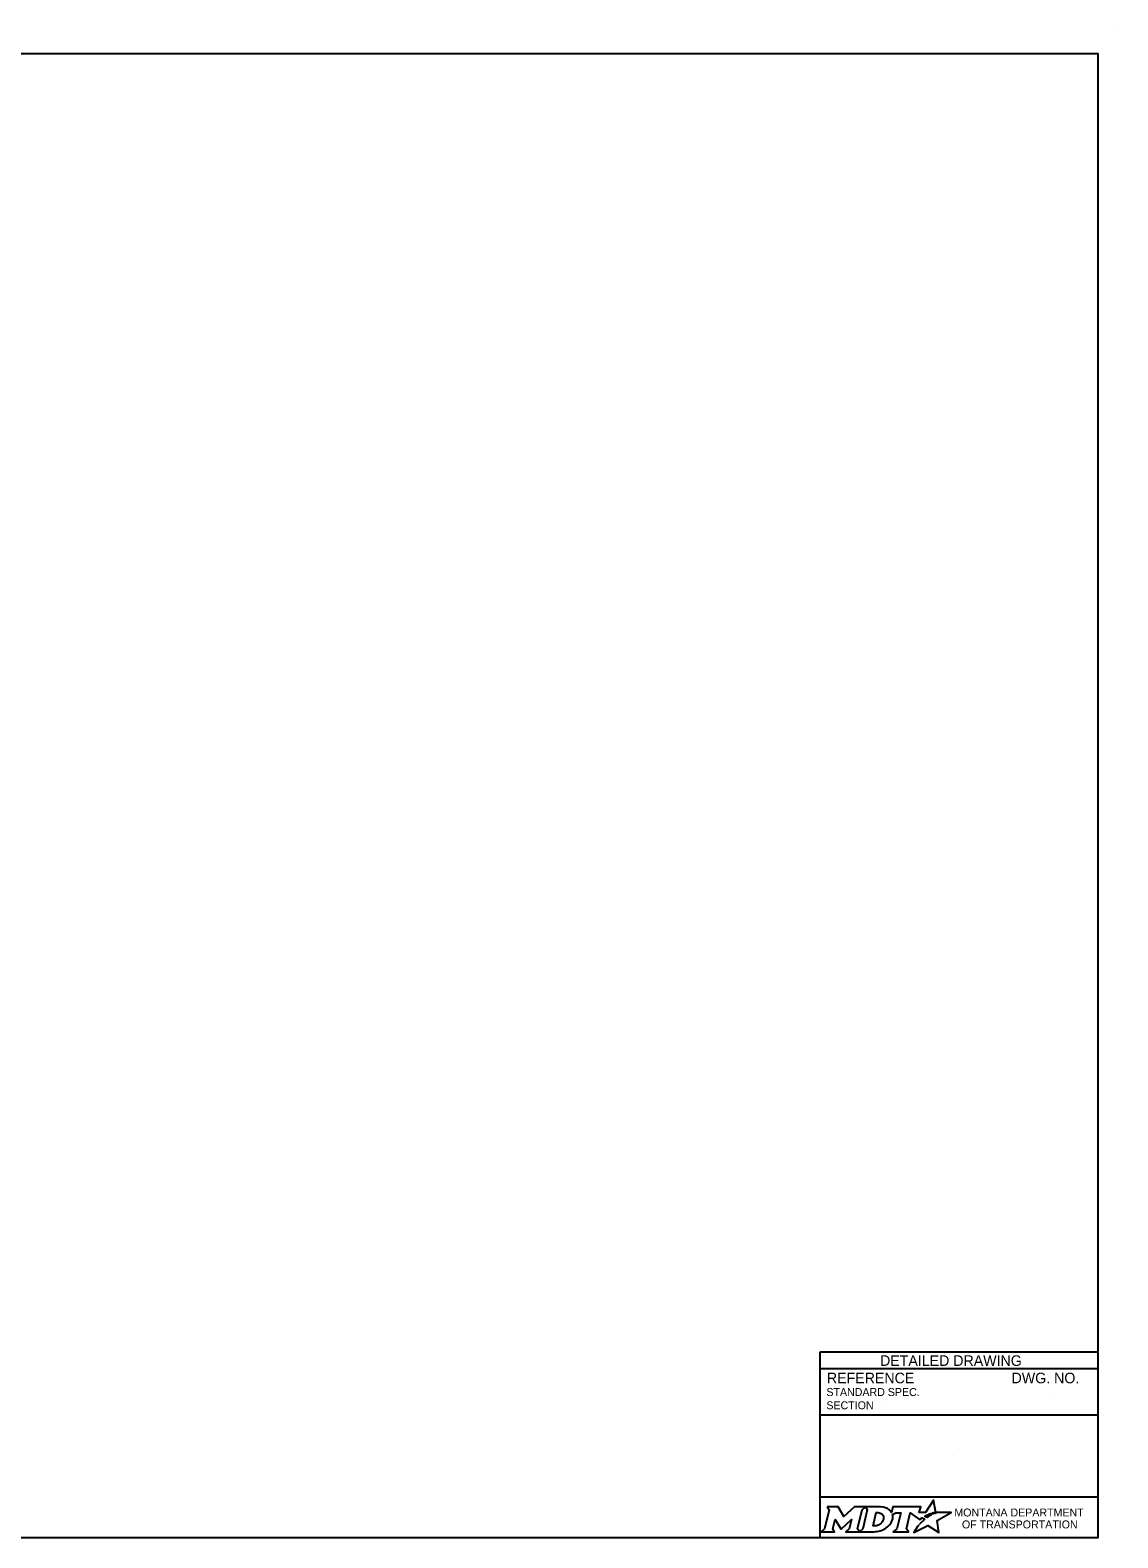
# Model space of a CAD drawing. Extents: x 49990.8 to 50021, y 49987.6 to 50011.4.
# Drawn here: x 50008.69 to 50016.9, y 49987.8 to 49999.18 of the extents above; entities that cross this region are included whole.
import ezdxf

# ---------------------------------------------------------------- set-up
doc = ezdxf.new("R2010")
doc.units = 0
for name, color, linetype in [('Default', 7, 'Continuous'), ('Level 1', 7, 'Continuous'), ('Level 5', 7, 'Continuous')]:
    doc.layers.add(name, color=color, linetype=linetype)

msp = doc.modelspace()

# ---------------------------------------------------------------- linework, layer by layer
at = {"layer": 'Default'}
for points in [[(50015.513, 49987.981), (50015.502, 49987.987), (50015.514, 49987.99), (50015.526, 49987.991), (50015.508, 49988.082), (50015.449, 49987.99), (50015.401, 49987.99), (50015.412, 49988.034), (50015.202, 49988.034), (50015.192, 49987.991), (50015.186, 49988)], [(50014.706, 49988.034), (50014.72, 49988.01), (50014.686, 49987.867), (50014.66, 49987.845), (50014.762, 49987.845), (50014.749, 49987.867), (50014.765, 49987.937), (50014.809, 49987.868), (50014.814, 49987.868), (50014.889, 49987.938), (50014.872, 49987.867), (50014.848, 49987.845), (50014.949, 49987.845), (50014.936, 49987.868), (50014.969, 49988.011)], [(50014.969, 49988.011), (50014.994, 49988.034), (50014.912, 49988.034), (50014.832, 49987.961), (50014.788, 49988.034), (50014.706, 49988.034)], [(50015.108, 49988.034), (50014.994, 49988.034), (50015.009, 49988.011), (50014.975, 49987.867), (50014.949, 49987.845), (50015.06, 49987.845)], [(50015.132, 49987.947), (50015.13, 49987.939), (50015.127, 49987.93), (50015.123, 49987.922), (50015.118, 49987.914), (50015.111, 49987.907), (50015.103, 49987.901), (50015.095, 49987.896), (50015.086, 49987.892), (50015.077, 49987.89), (50015.067, 49987.889), (50015.052, 49987.889), (50015.075, 49987.989), (50015.091, 49987.989), (50015.099, 49987.988), (50015.106, 49987.986), (50015.113, 49987.983), (50015.119, 49987.979), (50015.124, 49987.974), (50015.128, 49987.968), (50015.13, 49987.962), (50015.132, 49987.955), (50015.132, 49987.952), (50015.132, 49987.947)], [(50015.199, 49987.975), (50015.224, 49987.988), (50015.261, 49987.988), (50015.232, 49987.867), (50015.205, 49987.845), (50015.321, 49987.845), (50015.304, 49987.867), (50015.332, 49987.988), (50015.403, 49987.936), (50015.424, 49987.951), (50015.444, 49987.94)], [(50015.388, 49987.884), (50015.373, 49987.86), (50015.368, 49987.852), (50015.362, 49987.844), (50015.36, 49987.839), (50015.465, 49987.893), (50015.549, 49987.838), (50015.536, 49987.93), (50015.643, 49987.989), (50015.594, 49987.989), (50015.564, 49987.99), (50015.543, 49987.99), (50015.536, 49987.989), (50015.531, 49987.987), (50015.523, 49987.985), (50015.513, 49987.981)], [(50015.462, 49987.954), (50015.46, 49987.952), (50015.442, 49987.961), (50015.452, 49987.967), (50015.456, 49987.969), (50015.465, 49987.973), (50015.47, 49987.976), (50015.478, 49987.979), (50015.485, 49987.982), (50015.497, 49987.974), (50015.493, 49987.972), (50015.489, 49987.97), (50015.484, 49987.967), (50015.479, 49987.965), (50015.478, 49987.963), (50015.475, 49987.962), (50015.472, 49987.96), (50015.47, 49987.959), (50015.467, 49987.957), (50015.465, 49987.955), (50015.462, 49987.954)], [(50015.106, 49987.852), (50015.114, 49987.855), (50015.127, 49987.86), (50015.148, 49987.871)], [(50015.402, 49987.9), (50015.402, 49987.9)]]:
    msp.add_lwpolyline(points, dxfattribs=at)
for centre, radius, start, end in [((50015.087, 49987.973), 0.118, 300.9103, 339.1383), ((50015.131, 49987.955), 0.0709, 339.5329, 15.8582)]:
    msp.add_arc(centre, radius, start, end, dxfattribs=at)
for centre, major_axis, ratio, start_param, end_param in [((50015.106, 49987.986), (0.0834, -0.0037), 0.568097, 0.61298, 1.570796), ((50015.161, 49987.994), (0.0361, -0.0295), 0.469099, 1.225588, 1.570796), ((50015.433, 49987.93), (-0.0112, -0.0097), 0.021651, 3.157348, 6.283185), ((50015.06, 49987.993), (0, 0.148), 0.987302, 3.139398, 3.456847), ((50015.395, 49987.892), (-0.00694, -0.00806), 0.008222, 0, 3.137361), ((50015.412, 49987.911), (-0.0098, -0.0102), 0.016458, 3.141593, 6.279097)]:
    msp.add_ellipse(centre, major_axis=major_axis, ratio=ratio, start_param=start_param, end_param=end_param, dxfattribs=at)
at = {"layer": 'Level 1'}
msp.add_line((50016.9, 49999.176), (50016.9, 49999.176), dxfattribs=at)
msp.add_lwpolyline([(49999.384, 49998.999), (50016.75, 49998.999), (50016.75, 49987.799), (49999.384, 49987.799)], close=True, dxfattribs=at)
at = {"layer": 'Level 5'}
for p, q in [((50016.75, 49989.199), (50014.65, 49989.199)), ((50014.65, 49989.199), (50014.65, 49987.799)), ((50016.75, 49989.074), (50014.65, 49989.074)), ((50016.386, 49988.859), (50016.386, 49988.859)), ((50016.75, 49988.724), (50014.65, 49988.724)), ((50015.144, 49988.799), (50015.144, 49988.799)), ((50015.7, 49988.475), (50015.7, 49988.475)), ((50016.75, 49988.106), (50014.65, 49988.106))]:
    msp.add_line(p, q, dxfattribs=at)

# ---------------------------------------------------------------- texts
at = {"layer": 'Default'}
for s, p in [('MONTANA DEPARTMENT', (50015.666, 49987.96)), ('OF TRANSPORTATION', (50015.723, 49987.87))]:
    msp.add_text(s, height=0.06, dxfattribs=at).set_placement(p)
at = {"layer": 'Level 5'}
for s, height, p in [('DETAILED DRAWING', 0.08, (50015.105, 49989.096)), ('REFERENCE', 0.08, (50014.704, 49988.965)), ('DWG. NO.', 0.08, (50016.098, 49988.965)), ('STANDARD SPEC.', 0.06, (50014.7, 49988.869)), ('SECTION', 0.06, (50014.7, 49988.769))]:
    msp.add_text(s, height=height, dxfattribs=at).set_placement(p)

doc.saveas('drawing.dxf')
